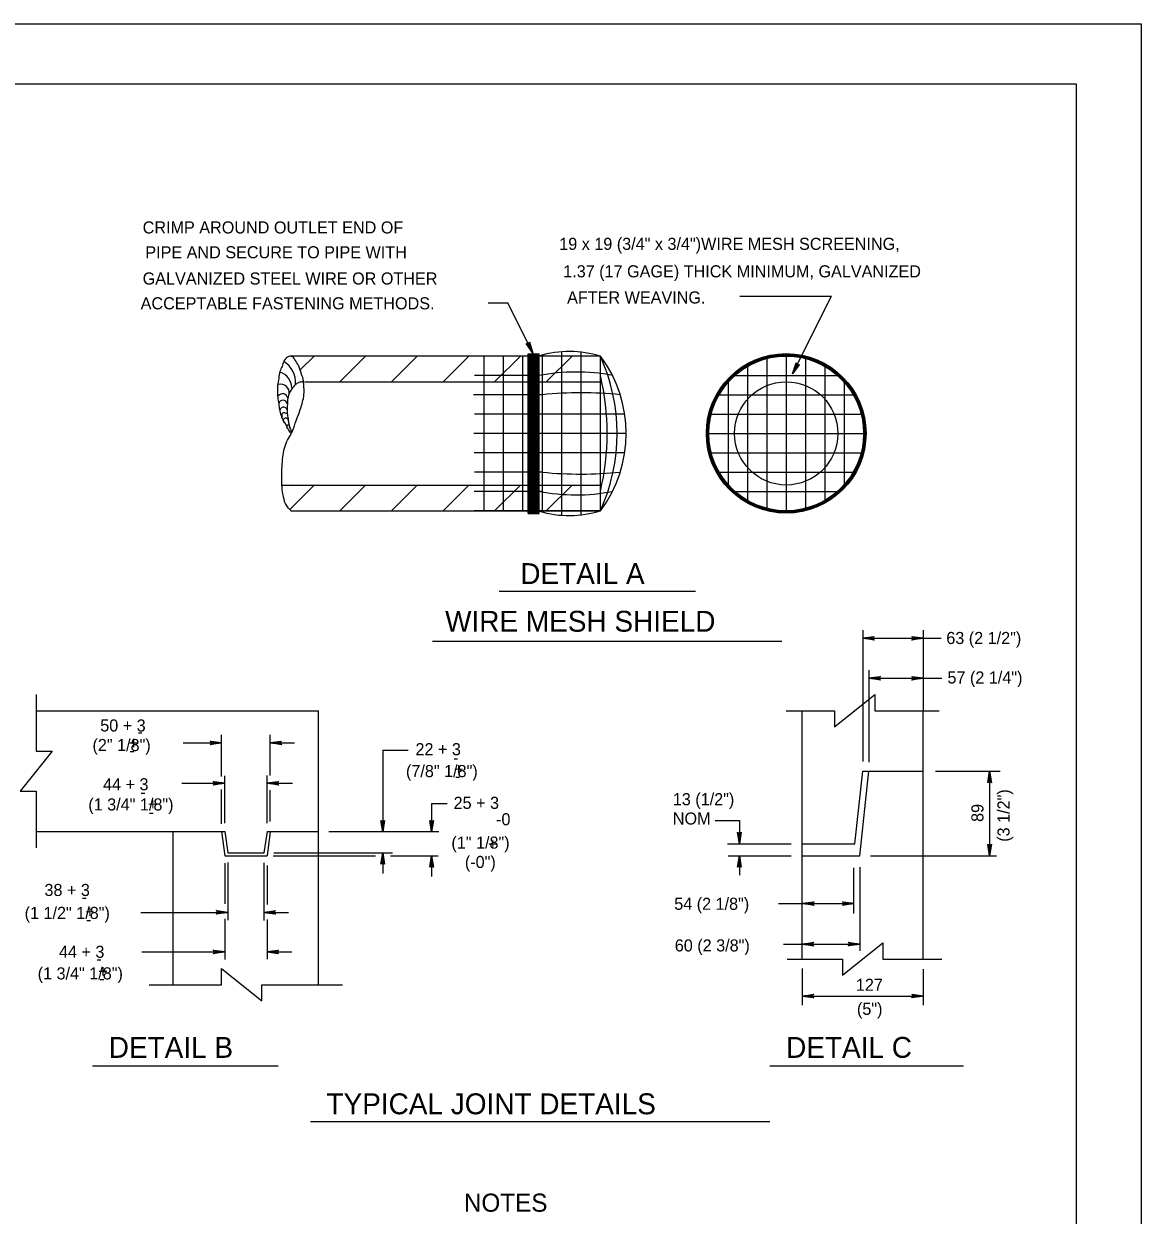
# Model space of a CAD drawing. Extents: x 638443 to 639347, y 298405 to 298999.
# Drawn here: x 639007.2 to 639284.3, y 298703.3 to 298999 of the extents above; entities that cross this region are included whole.
import ezdxf

# ---------------------------------------------------------------- set-up
doc = ezdxf.new("R2010")
doc.units = 0
for name, color, linetype in [('1', 7, 'Continuous'), ('2', 7, 'Continuous'), ('3', 7, 'Continuous'), ('PLT-BNDY', 7, 'Continuous')]:
    doc.layers.add(name, color=color, linetype=linetype)

msp = doc.modelspace()

# ---------------------------------------------------------------- linework, layer by layer
at = {"layer": '1'}
msp.add_lwpolyline([(639268.31, 298419.95), (639268.31, 298983.95), (638482.31, 298983.95), (638482.31, 298419.95), (639268.31, 298419.95), (639268.31, 298446.31), (639068.31, 298446.31), (639068.31, 298510.99), (639268.31, 298510.99), (639268.31, 298539.95), (639068.31, 298539.95), (639068.31, 298419.95), (639147.11, 298419.95), (639147.11, 298446.31), (639147.11, 298419.95), (639224.11, 298419.95), (639224.11, 298446.31), (639224.11, 298434), (639268.31, 298434)], dxfattribs=at)
at = {"layer": '2'}
for p, q in [((639184.81, 298931.35), (639207.48, 298931.35)), ((639197.85, 298912.07), (639207.48, 298931.35)), ((639122.39, 298929.71), (639127.24, 298929.71)), ((639133.46, 298917.26), (639127.24, 298929.71)), ((639150.19, 298916.51), (639073.39, 298916.51)), ((639073.49, 298916.37), (639073.63, 298916.51)), ((639075.71, 298913.06), (639079.16, 298916.51)), ((639085.56, 298910.11), (639091.96, 298916.51)), ((639098.36, 298910.11), (639104.76, 298916.51)), ((639111.16, 298910.11), (639117.56, 298916.51)), ((639150.19, 298916.51), (639118.93, 298916.51)), ((639121.39, 298878.11), (639121.39, 298916.51)), ((639123.96, 298910.11), (639130.36, 298916.51)), ((639126.19, 298878.11), (639126.19, 298916.51)), ((639130.99, 298878.11), (639130.99, 298916.51)), ((639132.27, 298877.42), (639132.27, 298917.03)), ((639132.27, 298917.03), (639135.03, 298917.03)), ((639132.43, 298877.42), (639132.43, 298917.03)), ((639132.63, 298877.42), (639132.63, 298917.03)), ((639132.83, 298877.42), (639132.83, 298917.03)), ((639133.03, 298877.42), (639133.03, 298917.03)), ((639133.23, 298877.42), (639133.23, 298917.03)), ((639133.43, 298877.42), (639133.43, 298917.03)), ((639133.63, 298877.42), (639133.63, 298917.03)), ((639133.83, 298877.42), (639133.83, 298917.03)), ((639134.03, 298877.42), (639134.03, 298917.03)), ((639134.23, 298877.42), (639134.23, 298917.03)), ((639134.43, 298877.42), (639134.43, 298917.03)), ((639134.63, 298877.42), (639134.63, 298917.03)), ((639134.83, 298877.42), (639134.83, 298917.03)), ((639135.03, 298877.42), (639135.03, 298917.03)), ((639135.79, 298878.11), (639135.79, 298916.51)), ((639136.76, 298910.11), (639143.16, 298916.51)), ((639140.59, 298876.99), (639140.59, 298917.58)), ((639145.39, 298877.09), (639145.39, 298917.48)), ((639150.19, 298878.11), (639150.19, 298916.51)), ((639191.47, 298916.51), (639191.47, 298878.11)), ((639196.27, 298916.51), (639196.27, 298878.11)), ((639201.07, 298916.51), (639201.07, 298878.11)), ((639186.67, 298914.62), (639186.67, 298879.99)), ((639205.87, 298914.62), (639205.87, 298879.99)), ((639076.78, 298910.11), (639150.19, 298910.11)), ((639134.93, 298911.71), (639118.98, 298911.71)), ((639181.87, 298910.89), (639181.87, 298883.72)), ((639182.68, 298911.71), (639209.86, 298911.71)), ((639210.67, 298910.89), (639210.67, 298883.72)), ((639135.81, 298906.91), (639118.69, 298906.91)), ((639178.95, 298906.91), (639213.59, 298906.91)), ((639156.23, 298902.11), (639118.93, 298902.11)), ((639177.07, 298902.11), (639215.47, 298902.11)), ((639156.59, 298897.31), (639118.8, 298897.31)), ((639150.19, 298897.31), (639150.19, 298897.31)), ((639151.47, 298897.31), (639151.47, 298897.31)), ((639152.75, 298897.31), (639152.75, 298897.31)), ((639154.03, 298897.31), (639154.03, 298897.31)), ((639155.31, 298897.31), (639155.31, 298897.31)), ((639156.59, 298897.31), (639156.59, 298897.31)), ((639177.07, 298897.31), (639215.47, 298897.31)), ((639156.23, 298892.51), (639118.86, 298892.51)), ((639177.07, 298892.51), (639215.47, 298892.51)), ((639135.81, 298887.71), (639118.98, 298887.71)), ((639178.95, 298887.71), (639213.59, 298887.71)), ((639071.35, 298884.51), (639150.19, 298884.51)), ((639073.12, 298878.47), (639079.16, 298884.51)), ((639073.49, 298884.37), (639073.63, 298884.51)), ((639085.56, 298878.11), (639091.96, 298884.51)), ((639098.36, 298878.11), (639104.76, 298884.51)), ((639111.16, 298878.11), (639117.56, 298884.51)), ((639123.96, 298878.11), (639130.36, 298884.51)), ((639136.76, 298878.11), (639143.16, 298884.51)), ((639135.51, 298882.91), (639118.86, 298882.91)), ((639182.68, 298882.91), (639209.86, 298882.91)), ((639073.39, 298878.11), (639150.19, 298878.11)), ((639150.19, 298878.11), (639118.86, 298878.11)), ((639132.27, 298877.42), (639135.03, 298877.42)), ((639125.1, 298858.13), (639173.77, 298858.13)), ((639215.25, 298848.45), (639215.25, 298815.93)), ((639230.25, 298848.51), (639230.25, 298828.5)), ((639108.58, 298845.8), (639195.19, 298845.8)), ((639215.25, 298846.48), (639230.25, 298846.48)), ((639230.25, 298846.48), (639234.7, 298846.48)), ((639216.75, 298838.53), (639216.75, 298815.76)), ((639216.75, 298836.56), (639230.25, 298836.56)), ((639230.25, 298836.56), (639234.87, 298836.56)), ((639010.29, 298828.5), (639080.25, 298828.5)), ((639080.25, 298760.5), (639080.25, 298828.5)), ((639200.25, 298766.88), (639200.25, 298828.5)), ((639230.25, 298766.88), (639230.25, 298828.5)), ((639056.25, 298812.15), (639056.25, 298822.5)), ((639068.25, 298812.41), (639068.25, 298822.5)), ((639046.67, 298820.5), (639056.25, 298820.5)), ((639068.25, 298820.5), (639074.28, 298820.5)), ((639096.21, 298818.7), (639096.21, 298798.42)), ((639096.21, 298818.7), (639102.55, 298818.7)), ((639057, 298800.62), (639057, 298812.33)), ((639067.5, 298800.62), (639067.5, 298812.42)), ((639213.33, 298795.5), (639215.25, 298813.5)), ((639214.5, 298792.5), (639216.75, 298813.5)), ((639215.25, 298813.5), (639230.25, 298813.5)), ((639233.27, 298813.5), (639249.34, 298813.5)), ((639246.73, 298813.5), (639246.73, 298792.5)), ((639046.35, 298810.5), (639057, 298810.5)), ((639067.5, 298810.5), (639073.85, 298810.5)), ((639056.25, 298800.45), (639056.25, 298808.92)), ((639068.25, 298800.98), (639068.25, 298808.79)), ((639178.63, 298801.24), (639184.66, 298801.24)), ((639184.66, 298801.24), (639184.66, 298795.5)), ((639010.25, 298798.5), (639044.25, 298798.5)), ((639044.25, 298760.5), (639044.25, 298798.5)), ((639044.25, 298798.5), (639057, 298798.5)), ((639056.25, 298798.5), (639057, 298792.5)), ((639057, 298798.5), (639057.75, 298793.25)), ((639067.5, 298798.5), (639066.75, 298793.25)), ((639067.5, 298798.5), (639080.25, 298798.5)), ((639068.25, 298798.5), (639067.5, 298792.5)), ((639082.8, 298798.5), (639110.14, 298798.5)), ((639181.74, 298795.5), (639197.47, 298795.5)), ((639200.25, 298795.5), (639213.33, 298795.5)), ((639057, 298792.5), (639067.5, 298792.5)), ((639057.75, 298793.25), (639066.76, 298793.25)), ((639069.06, 298792.5), (639094.4, 298792.5)), ((639069.17, 298793.25), (639098.59, 298793.25)), ((639096.21, 298793.25), (639096.21, 298788.08)), ((639098.15, 298792.5), (639109.95, 298792.5)), ((639181.91, 298792.5), (639197.47, 298792.5)), ((639184.66, 298792.5), (639184.66, 298787.7)), ((639200.25, 298792.5), (639214.5, 298792.5)), ((639217.18, 298792.5), (639248.47, 298792.5)), ((639057, 298790.65), (639057, 298780.58)), ((639057.75, 298790.83), (639057.75, 298776.55)), ((639066.75, 298790.74), (639066.75, 298776.44)), ((639067.5, 298790.12), (639067.5, 298780.45)), ((639213, 298789.49), (639213, 298778.21)), ((639214.5, 298789.66), (639214.5, 298768.95)), ((639194.39, 298780.64), (639200.34, 298780.64)), ((639200.34, 298780.64), (639213.09, 298780.64)), ((639036.24, 298778.46), (639057.75, 298778.46)), ((639057, 298776.83), (639057, 298766.76)), ((639066.75, 298778.46), (639072.87, 298778.46)), ((639067.5, 298776.7), (639067.5, 298766.88)), ((639036.45, 298768.63), (639057, 298768.63)), ((639067.5, 298768.63), (639073.64, 298768.63)), ((639195.57, 298770.57), (639200.25, 298770.57)), ((639200.25, 298770.57), (639214.5, 298770.57)), ((639200.25, 298764.56), (639200.25, 298755.45)), ((639230.25, 298764.39), (639230.25, 298755.45)), ((639200.25, 298757.7), (639230.25, 298757.7)), ((639024.25, 298740.36), (639070.25, 298740.36)), ((639192.25, 298740.36), (639240.25, 298740.36)), ((639078.25, 298726.56), (639192.25, 298726.56))]:
    msp.add_line(p, q, dxfattribs=at)
for points in [[(639132.55, 298919.85), (639132.42, 298919.67), (639133.46, 298917.26), (639132.55, 298919.85), (639132.59, 298920.03), (639133.46, 298917.26), (639132.17, 298919.55), (639131.95, 298919.55), (639133.46, 298917.26), (639131.77, 298919.62), (639131.95, 298919.55)], [(639199.37, 298914.36), (639199.15, 298914.36), (639197.85, 298912.07), (639199.37, 298914.36), (639199.54, 298914.43), (639197.85, 298912.07), (639198.9, 298914.48), (639198.77, 298914.65), (639197.85, 298912.07), (639198.72, 298914.84), (639198.77, 298914.65)], [(639217.98, 298846.14), (639217.88, 298846.34), (639215.25, 298846.48), (639217.98, 298846.14), (639218.12, 298846.02), (639215.25, 298846.48), (639217.87, 298846.61), (639217.97, 298846.8), (639215.25, 298846.48), (639218.12, 298846.94), (639217.97, 298846.8)], [(639227.53, 298846.82), (639227.63, 298846.62), (639230.25, 298846.48), (639227.53, 298846.82), (639227.39, 298846.94), (639230.25, 298846.48), (639227.63, 298846.35), (639227.54, 298846.16), (639230.25, 298846.48), (639227.39, 298846.02), (639227.54, 298846.16)], [(639219.48, 298836.22), (639219.38, 298836.42), (639216.75, 298836.56), (639219.48, 298836.22), (639219.62, 298836.1), (639216.75, 298836.56), (639219.37, 298836.69), (639219.47, 298836.88), (639216.75, 298836.56), (639219.62, 298837.02), (639219.47, 298836.88)], [(639227.53, 298836.9), (639227.63, 298836.7), (639230.25, 298836.56), (639227.53, 298836.9), (639227.39, 298837.02), (639230.25, 298836.56), (639227.63, 298836.43), (639227.54, 298836.24), (639230.25, 298836.56), (639227.39, 298836.1), (639227.54, 298836.24)], [(639010.25, 298832.5), (639010.25, 298818.5), (639014.25, 298818.5), (639006.25, 298808.5), (639010.25, 298808.5), (639010.25, 298794.5)], [(639196.25, 298828.5), (639208.25, 298828.5), (639208.25, 298824.5), (639218.25, 298832.5), (639218.25, 298828.5), (639234.25, 298828.5)], [(639053.53, 298820.84), (639053.63, 298820.65), (639056.25, 298820.5), (639053.53, 298820.84), (639053.39, 298820.96), (639056.25, 298820.5), (639053.63, 298820.37), (639053.54, 298820.18), (639056.25, 298820.5), (639053.39, 298820.05), (639053.54, 298820.18)], [(639070.98, 298820.16), (639070.88, 298820.36), (639068.25, 298820.5), (639070.98, 298820.16), (639071.12, 298820.04), (639068.25, 298820.5), (639070.87, 298820.63), (639070.97, 298820.83), (639068.25, 298820.5), (639071.12, 298820.96), (639070.97, 298820.83)], [(639246.38, 298810.78), (639246.58, 298810.88), (639246.73, 298813.5), (639246.38, 298810.78), (639246.26, 298810.64), (639246.73, 298813.5), (639246.86, 298810.88), (639247.05, 298810.79), (639246.73, 298813.5), (639247.18, 298810.64), (639247.05, 298810.79)], [(639054.28, 298810.84), (639054.38, 298810.65), (639057, 298810.5), (639054.28, 298810.84), (639054.14, 298810.96), (639057, 298810.5), (639054.38, 298810.37), (639054.29, 298810.18), (639057, 298810.5), (639054.14, 298810.05), (639054.29, 298810.18)], [(639070.23, 298810.16), (639070.13, 298810.36), (639067.5, 298810.5), (639070.23, 298810.16), (639070.37, 298810.04), (639067.5, 298810.5), (639070.12, 298810.63), (639070.22, 298810.83), (639067.5, 298810.5), (639070.37, 298810.96), (639070.22, 298810.83)], [(639096.55, 298801.15), (639096.35, 298801.05), (639096.21, 298798.42), (639096.55, 298801.15), (639096.67, 298801.29), (639096.21, 298798.42), (639096.08, 298801.04), (639095.89, 298801.14), (639096.21, 298798.42), (639095.75, 298801.29), (639095.89, 298801.14)], [(639185, 298798.23), (639184.8, 298798.12), (639184.66, 298795.5), (639185, 298798.23), (639185.12, 298798.37), (639184.66, 298795.5), (639184.53, 298798.12), (639184.33, 298798.22), (639184.66, 298795.5), (639184.2, 298798.37), (639184.33, 298798.22)], [(639095.87, 298790.53), (639096.07, 298790.63), (639096.21, 298793.25), (639095.87, 298790.53), (639095.75, 298790.39), (639096.21, 298793.25), (639096.34, 298790.63), (639096.53, 298790.54), (639096.21, 298793.25), (639096.67, 298790.39), (639096.53, 298790.54)], [(639184.31, 298789.78), (639184.51, 298789.88), (639184.66, 298792.5), (639184.31, 298789.78), (639184.19, 298789.64), (639184.66, 298792.5), (639184.79, 298789.88), (639184.98, 298789.79), (639184.66, 298792.5), (639185.11, 298789.64), (639184.98, 298789.79)], [(639203.07, 298780.3), (639202.96, 298780.5), (639200.34, 298780.64), (639203.07, 298780.3), (639203.21, 298780.18), (639200.34, 298780.64), (639202.96, 298780.77), (639203.06, 298780.97), (639200.34, 298780.64), (639203.21, 298781.1), (639203.06, 298780.97)], [(639210.37, 298780.99), (639210.47, 298780.79), (639213.09, 298780.64), (639210.37, 298780.99), (639210.23, 298781.11), (639213.09, 298780.64), (639210.47, 298780.51), (639210.38, 298780.32), (639213.09, 298780.64), (639210.23, 298780.19), (639210.38, 298780.32)], [(639055.03, 298778.81), (639055.13, 298778.61), (639057.75, 298778.46), (639055.03, 298778.81), (639054.89, 298778.93), (639057.75, 298778.46), (639055.13, 298778.33), (639055.04, 298778.14), (639057.75, 298778.46), (639054.89, 298778.01), (639055.04, 298778.14)], [(639069.48, 298778.12), (639069.38, 298778.32), (639066.75, 298778.46), (639069.48, 298778.12), (639069.62, 298778), (639066.75, 298778.46), (639069.37, 298778.59), (639069.47, 298778.79), (639066.75, 298778.46), (639069.62, 298778.92), (639069.47, 298778.79)], [(639196.51, 298766.88), (639210.2, 298766.88), (639210.2, 298762.88), (639220.2, 298770.88), (639220.2, 298766.88), (639234.87, 298766.88)], [(639202.98, 298770.23), (639202.88, 298770.43), (639200.25, 298770.57), (639202.98, 298770.23), (639203.12, 298770.11), (639200.25, 298770.57), (639202.87, 298770.7), (639202.97, 298770.9), (639200.25, 298770.57), (639203.12, 298771.03), (639202.97, 298770.9)], [(639211.78, 298770.92), (639211.88, 298770.72), (639214.5, 298770.57), (639211.78, 298770.92), (639211.64, 298771.04), (639214.5, 298770.57), (639211.88, 298770.44), (639211.79, 298770.25), (639214.5, 298770.57), (639211.64, 298770.12), (639211.79, 298770.25)], [(639054.28, 298768.98), (639054.38, 298768.78), (639057, 298768.63), (639054.28, 298768.98), (639054.14, 298769.1), (639057, 298768.63), (639054.38, 298768.5), (639054.29, 298768.31), (639057, 298768.63), (639054.14, 298768.18), (639054.29, 298768.31)], [(639070.23, 298768.29), (639070.13, 298768.49), (639067.5, 298768.63), (639070.23, 298768.29), (639070.37, 298768.17), (639067.5, 298768.63), (639070.12, 298768.76), (639070.22, 298768.96), (639067.5, 298768.63), (639070.37, 298769.09), (639070.22, 298768.96)], [(639038.25, 298760.5), (639056.25, 298760.5), (639056.25, 298764.5), (639066.25, 298756.5), (639066.25, 298760.5), (639086.25, 298760.5)], [(639227.53, 298758.05), (639227.63, 298757.85), (639230.25, 298757.7), (639227.53, 298758.05), (639227.39, 298758.17), (639230.25, 298757.7), (639227.63, 298757.57), (639227.54, 298757.38), (639230.25, 298757.7), (639227.39, 298757.25), (639227.54, 298757.38)]]:
    msp.add_lwpolyline(points, dxfattribs=at)
for radius in [19.8, 19.6, 19.4, 19.2, 12.8]:
    msp.add_circle((639196.27, 298897.31), radius, dxfattribs=at)
for centre, radius, start, end in [((639142.43, 298891.45), 26.19, 72.7594, 106.3688), ((639124.59, 298897.31), 32, 323.1301, 36.8699), ((639107.79, 298897.31), 46.54, 335.6359, 24.3641), ((639068.67, 298910.03), 5.92, 354.8555, 59.6708), ((639069.3, 298908.4), 4.38, 2.757, 70.3813), ((639144.17, 298864.23), 48.32, 79.266, 101.0155), ((639089.41, 298897.31), 62.46, 346.6703, 13.3297), ((639071.34, 298905.8), 1.35, 10.9894, 140.8654), ((639070.9, 298907.42), 2.09, 350.3069, 105.1317), ((639145.43, 298809.41), 97.98, 84.3259, 95.6361), ((639071.45, 298904.53), 1.05, 8.8886, 171.1114), ((639071.6, 298902.92), 0.914, 14.4815, 191.8386), ((639071.79, 298901.8), 0.647, 26.1102, 221.1114), ((639072.17, 298900.51), 0.63, 346.8875, 261.2044), ((639072.74, 298899.02), 0.387, 316.6855, 259.5583), ((639145.43, 298985.2), 97.98, 264.3639, 275.6741), ((639144.17, 298930.38), 48.32, 258.9845, 280.734), ((639142.43, 298903.12), 26.19, 253.6312, 287.2406)]:
    msp.add_arc(centre, radius, start, end, dxfattribs=at)
for points in [[(639073.49, 298878.11), (639072.31, 298879.47), (639071.6, 298881.49), (639071.24, 298883.98), (639071.18, 298886.23), (639071.24, 298889.2), (639071.42, 298891.4), (639071.84, 298893.66), (639072.55, 298895.62), (639073.56, 298897.34), (639074.51, 298899.83), (639075.16, 298901.61), (639075.93, 298903.81), (639076.41, 298905.53), (639076.7, 298907.49), (639076.64, 298909.09), (639076.46, 298910.75), (639075.93, 298912.35), (639075.28, 298914.2), (639074.51, 298915.5), (639073.49, 298916.51), (639072.31, 298916.03), (639071.66, 298915.14), (639071.24, 298913.96), (639070.7, 298912.71), (639070.41, 298910.99), (639070.11, 298909.21), (639070.11, 298907.73), (639070.17, 298906.24), (639070.41, 298904.64), (639070.59, 298903.16), (639071, 298901.79), (639071.6, 298900.3), (639072.37, 298899.17), (639072.67, 298898.41), (639073.38, 298897.34)], [(639076.46, 298910.11), (639075.34, 298909.92), (639074.51, 298909.39), (639073.67, 298908.38), (639073.14, 298907.49), (639072.67, 298906.06), (639072.55, 298904.52), (639072.49, 298903.21), (639072.55, 298902.02), (639072.78, 298900.6), (639072.96, 298899.48), (639073.2, 298898.64), (639073.56, 298897.45)]]:
    msp.add_spline(points, degree=3, dxfattribs=at)
at = {"layer": '3'}
for p, q in [((639108.32, 298805.49), (639108.32, 298798.42)), ((639108.32, 298805.49), (639112.17, 298805.49)), ((639108.32, 298792.5), (639108.32, 298787.33))]:
    msp.add_line(p, q, dxfattribs=at)
for points in [[(639108.66, 298801.15), (639108.46, 298801.05), (639108.32, 298798.42), (639108.66, 298801.15), (639108.78, 298801.29), (639108.32, 298798.42), (639108.19, 298801.04), (639108, 298801.14), (639108.32, 298798.42), (639107.86, 298801.29), (639108, 298801.14)], [(639247.07, 298795.23), (639246.87, 298795.12), (639246.73, 298792.5), (639247.07, 298795.23), (639247.19, 298795.37), (639246.73, 298792.5), (639246.6, 298795.12), (639246.4, 298795.22), (639246.73, 298792.5), (639246.27, 298795.37), (639246.4, 298795.22)], [(639107.98, 298789.78), (639108.18, 298789.88), (639108.32, 298792.5), (639107.98, 298789.78), (639107.86, 298789.64), (639108.32, 298792.5), (639108.45, 298789.88), (639108.64, 298789.79), (639108.32, 298792.5), (639108.78, 298789.64), (639108.64, 298789.79)], [(639202.98, 298757.36), (639202.88, 298757.56), (639200.25, 298757.7), (639202.98, 298757.36), (639203.12, 298757.24), (639200.25, 298757.7), (639202.87, 298757.83), (639202.97, 298758.03), (639200.25, 298757.7), (639203.12, 298758.16), (639202.97, 298758.03)]]:
    msp.add_lwpolyline(points, dxfattribs=at)
at = {"layer": 'PLT-BNDY'}
msp.add_lwpolyline([(638443.31, 298998.95), (639284.31, 298998.95), (639284.31, 298404.95), (638443.31, 298404.95)], close=True, dxfattribs=at)

# ---------------------------------------------------------------- texts
at = {"layer": '1'}
for s, p in [('(2" 1/8")', (639024.21, 298818.49)), ('+', (639033.27, 298819.07)), ('(7/8" 1/8")', (639101.97, 298812.02)), ('+', (639113.87, 298812.54)), ('(1 3/4" 1/8")', (639023.18, 298803.74)), ('+', (639037.99, 298803.87)), ('(1" 1/8")', (639113.23, 298794.27)), ('+', (639122.35, 298793.97)), ('   (-0")', (639113.23, 298789.47)), ('(1 1/2" 1/8")', (639007.39, 298776.83)), ('+', (639022.37, 298777.15)), ('(1 3/4" 1/8")', (639010.62, 298761.82)), ('+', (639025.67, 298762.4)), ('(5")', (639213.82, 298753.02))]:
    msp.add_text(s, height=3, dxfattribs=at).set_placement(p)
at = {"layer": '2'}
for s, height, p in [('DETAIL A', 5.186, (639130.32, 298859.93)), ('WIRE MESH SHIELD', 5.186, (639111.67, 298848.1)), ('DETAIL B', 5.186, (639028.25, 298742.36)), ('DETAIL C', 5.186, (639196.25, 298742.36)), ('TYPICAL JOINT DETAILS', 5.186, (639082.25, 298728.36)), ('NOTES', 4.5, (639116.33, 298704.17))]:
    msp.add_text(s, height=height, dxfattribs=at).set_placement(p)
for s, p in [('(3 1/2")', (639251.67, 298795.98)), ('89', (639245.2, 298800.9))]:
    msp.add_text(s, height=3, rotation=90, dxfattribs=at).set_placement(p)
at = {"layer": '3'}
for s, p in [('CRIMP AROUND OUTLET END OF', (639036.66, 298946.93)), ('19 x 19 (3/4" x 3/4")WIRE MESH SCREENING,', (639139.98, 298942.86)), ('PIPE AND SECURE TO PIPE WITH', (639037.32, 298940.77)), ('GALVANIZED STEEL WIRE OR OTHER', (639036.66, 298934.26)), ('1.37 (17 GAGE) THICK MINIMUM, GALVANIZED', (639140.97, 298936.04)), ('ACCEPTABLE FASTENING METHODS.', (639036.16, 298928.1)), ('AFTER WEAVING.', (639141.93, 298929.55)), ('63 (2 1/2")', (639235.98, 298845.05)), ('57 (2 1/4")', (639236.27, 298835.25)), ('50 + 3', (639026.14, 298823.35)), ('-', (639035.37, 298821.83)), ('-', (639033.37, 298817.17)), ('22 + 3', (639104.32, 298817.45)), ('-', (639113.67, 298815.37)), ('44 + 3', (639026.84, 298808.75)), ('-', (639114.12, 298810.84)), ('-', (639036.1, 298806.83)), ('25 + 3', (639113.78, 298804.14)), ('13 (1/2")', (639168.15, 298805.05)), ('-', (639038.15, 298801.9)), ('-0', (639124.31, 298800.06)), ('NOM', (639168.15, 298800.25)), ('38 + 3', (639012.3, 298782.52)), ('-', (639021.55, 298780.82)), ('54 (2 1/8")', (639168.5, 298779.09)), ('-', (639022.58, 298775.25)), ('60 (2 3/8")', (639168.64, 298768.76)), ('44 + 3', (639015.9, 298767.18)), ('-', (639025.15, 298765.5)), ('127', (639213.56, 298758.99)), ('-', (639025.94, 298760.57))]:
    msp.add_text(s, height=3, dxfattribs=at).set_placement(p)

doc.saveas('drawing.dxf')
